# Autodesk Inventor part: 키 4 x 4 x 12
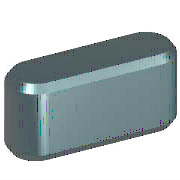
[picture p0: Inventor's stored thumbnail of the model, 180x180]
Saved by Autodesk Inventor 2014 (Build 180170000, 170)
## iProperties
IsCustomPart: 1
Created: 2012-02
Part Number: 키 4 x 4 x 12
Material: 강철, 연강
Description: 키 및 해당 키홈
Document SubType Name: Modeling
Standard: KS B 1311
Designer: mduedu
Standards Organization: KS
Language: ko-KR
Size Designation: 4 x 4 x 12
Categories: <MemberInstance><Categories><Category DisplayName="샤프트 부품" InternalName="7f7aeb1f-a693-4053-b835-cee3144e0d98" Mnemonic="SHFT"><Category DisplayName="키" Interna
Density: 7.86 g/cm^3
Mass: 1.38739 g
Surface Area: 1.94869 cm^2
Volume: 0.176513 cm^3
Appearance: Yellow
Author: mduedu
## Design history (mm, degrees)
sketch "스케치1"
  geometry: L1 (2, 2)-(10, 2); L2 (10, -2)-(2, -2); L3 (0, 9.4)-(0, -7.4) reference; L4 (-5, 0)-(30, 0) reference; L5 (12, 0)-(12, 7); A1 r 2 centre (2, 0) between (2, 2) and (2, -2); A2 r 2 centre (10, 0) between (10, -2) and (10, 2)
  constraints: 6 end point, 5 point on circle, 4 tangent, 3 point on line, 2 centre point, 1 horizontal, 1 parallel, 1 perpendicular
  dimensions: "d0" = 2 radius of A1 (= 0.5 x PB); "d13" = 2 radius of A2 (= 0.5 x PB); "d14" = 12 distance between parallel lines of L5 L3 (= NLG)
extrude "본체1" new body sketch "스케치1" taper "d3" = 0 deg; stored distance "d4" = 10
workplane "Work Plane3"
body "Solid1"
workplane "Work Plane1"
workplane "Work Plane2"
chamfer "모따기1" distance "d8" = 0.25 (= PHH); stored, may be unused: second distance "d9" = 0.25 (= PHH), angle "d15" = 45 deg
other parameters: "d1" = -2.5 (= -PNT), "d2" = 1.5 (= PH - PNT), "NLG" = 12 [user parameter; used in 3 equation terms], "PB" = 4 [user parameter; used in 2 equation terms], "PNT" = 2.5 [user parameter; used in 2 equation terms], "PH" = 4 [user parameter; used in 1 equation term], "PHH" = 0.25 [user parameter; used in 2 equation terms], "d10" = 0, "d16" = 0, "d17" = 0, "d18" = 0, "PLB2" = 12 (= NLG) [user parameter], "WDMAX" = 12 [user parameter], "PLB1" = 12 (= NLG) [user parameter], "RR" = 0.08 [user parameter], "PUEB" = 1.8 [user parameter]
